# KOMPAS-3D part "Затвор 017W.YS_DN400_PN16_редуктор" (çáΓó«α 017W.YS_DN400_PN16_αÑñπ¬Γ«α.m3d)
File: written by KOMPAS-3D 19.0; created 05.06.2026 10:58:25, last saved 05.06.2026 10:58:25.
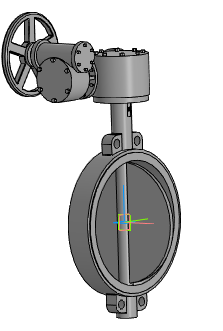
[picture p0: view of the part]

Document properties: Автор: Энергия; Полное имя файла: ..\..\..\3d для проектировщиков\x.x Тип 017W.Y(S) Затвор дисковый поворотный межфланцевый\Затвор 017W.Y(S)_DN50-DN1200_редуктор\Затвор 017W.YS_DN400_PN16_редуктор.a3d

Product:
- Part/product: Затвор 017W.YS_DN400_PN16_редуктор
    Масса: 126.248

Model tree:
1. Операция без истории:1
